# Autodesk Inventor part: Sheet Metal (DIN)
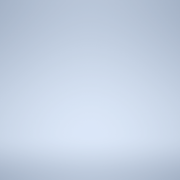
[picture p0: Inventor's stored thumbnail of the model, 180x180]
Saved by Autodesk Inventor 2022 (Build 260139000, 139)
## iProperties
Created: 2021-02
Part Number: Sheet Metal (DIN)
Material: Generico
Document SubType Name: Sheet Metal
Density: 1 g/cm^3
Sheet Metal Rule: Default_mm
Appearance: Default
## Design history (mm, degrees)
other parameters: "Spessore" = 0.5, "RaggioPiega" = 0.5 (= Spessore), "LarghezzaScaricoPiega" = 0.5 (= Spessore), "ProfonditàScaricoPiega" = 0.25 (= 0.5 x Spessore), "DimensioniScaricoAngolo" = 2 (= 4 x Spessore), "SeamGap" = 0.01, "ResiduoMinimo" = 1 (= 2 x Spessore), "RaggioTransizione" = 0.5 (= RaggioPiega), "Dimensione_raggio_Jacobi" = 0.5 (= RaggioPiega), "DimensioneGioco" = 0.5 (= Spessore)
